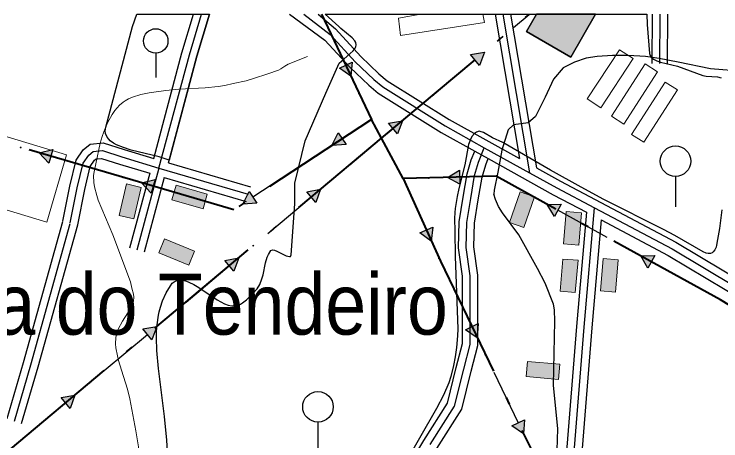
# Model space of a CAD drawing. Extents: x -64005 to -55000, y -89025 to -80000.
# Drawn here: x -59043 to -58117, y -80559 to -80000 of the extents above; entities that cross this region are included whole.
import ezdxf
from ezdxf.enums import TextEntityAlignment as Align

# ---------------------------------------------------------------- set-up
doc = ezdxf.new("R2010")
doc.units = 0
doc.header["$LTSCALE"] = 32
doc.linetypes.add('DOT_DASHED', pattern=[7.7, 5, -1.2, 0.3, -1.2])
doc.linetypes.add('LONG_DASHED', pattern=[7.5, 6, -1.5])
for name, color, linetype, lineweight in [('1', 7, 'Continuous', 25), ('16', 7, 'Continuous', 25), ('18', 7, 'Continuous', 25), ('2', 7, 'Continuous', 25), ('24', 7, 'Continuous', 25), ('3', 7, 'Continuous', 25), ('32', 7, 'Continuous', 25), ('39', 7, 'LONG_DASHED', 25), ('6', 7, 'Continuous', 25), ('7', 7, 'Continuous', 13), ('8', 7, 'Continuous', 25)]:
    doc.layers.add(name, color=color, linetype=linetype, lineweight=lineweight)
doc.layers.add('45', color=7, linetype='Continuous')

msp = doc.modelspace()

# ---------------------------------------------------------------- hatches: boundary and pattern name
at = {"layer": '18'}
for points in [[(-58444.9, -80052.94), (-58426.68, -80049.74), (-58433.02, -80067.12)], [(-58599.98, -80062.86), (-58601.46, -80081.3), (-58616.69, -80070.79)], [(-58552.21, -80142.86), (-58533.99, -80139.66), (-58540.33, -80157.04)], [(-58607.91, -80170.92), (-58626.38, -80171.99), (-58618.07, -80155.46)], [(-58997.52, -80195.16), (-59010.3, -80181.79), (-58992.33, -80177.41)], [(-58458.64, -80222.92), (-58474.89, -80214.08), (-58459.11, -80204.42)], [(-58863.17, -80234.47), (-58875.93, -80221.07), (-58857.95, -80216.72)], [(-58724.9, -80247.81), (-58743.37, -80248.88), (-58735.06, -80232.35)], [(-58659.52, -80232.77), (-58641.3, -80229.57), (-58647.64, -80246.95)], [(-58334.83, -80265.15), (-58344.4, -80249.31), (-58325.9, -80248.94)], [(-58494.36, -80279.2), (-58496.21, -80297.61), (-58511.22, -80286.81)], [(-58212.22, -80332.72), (-58221.78, -80316.88), (-58203.29, -80316.52)], [(-58766.84, -80322.68), (-58748.62, -80319.48), (-58754.96, -80336.86)], [(-58874.15, -80412.59), (-58855.93, -80409.4), (-58862.27, -80426.77)], [(-58434.72, -80405.59), (-58436.1, -80424.04), (-58451.39, -80413.63)], [(-58981.46, -80502.51), (-58963.24, -80499.31), (-58969.58, -80516.69)], [(-58373.94, -80531.71), (-58375.32, -80550.16), (-58390.61, -80539.75)]]:
    msp.add_hatch(color=256, dxfattribs=at).paths.add_polyline_path(points)
at = {"layer": '3'}
msp.add_hatch(color=256, dxfattribs=at).paths.add_polyline_path([(-58358.5, -80000), (-58371.58, -80022.88), (-58313.2, -80056.23), (-58281.07, -80000)])
at = {"layer": '7'}
for points in [[(-58895.71, -80222.52), (-58905.4, -80263.9), (-58885.93, -80268.46), (-58876.24, -80227.08)], [(-58836.11, -80243.16), (-58795.33, -80255.11), (-58789.71, -80235.92), (-58830.49, -80223.97)], [(-58379.9, -80233), (-58393.87, -80273.15), (-58374.98, -80279.72), (-58361.01, -80239.57)], [(-58319.38, -80258.65), (-58322.99, -80300.99), (-58303.06, -80302.69), (-58299.45, -80260.35)], [(-58853.24, -80312.98), (-58813.93, -80329.15), (-58806.32, -80310.66), (-58845.63, -80294.49)], [(-58323.78, -80320.93), (-58327.39, -80363.27), (-58307.46, -80364.97), (-58303.85, -80322.63)], [(-58271.06, -80320.32), (-58274.67, -80362.66), (-58254.74, -80364.36), (-58251.13, -80322.02)], [(-58372.01, -80475.07), (-58329.67, -80478.68), (-58327.97, -80458.75), (-58370.31, -80455.14)]]:
    msp.add_hatch(color=256, dxfattribs=at).paths.add_polyline_path(points)

# ---------------------------------------------------------------- linework, layer by layer
at = {"layer": '1'}
for points in [[(-58086.94, -80075.03), (-58130.16, -80071.76), (-58172.67, -80063.13), (-58197.69, -80057.93), (-58215.62, -80055.66), (-58238.24, -80054.09), (-58258.66, -80054.07), (-58278.98, -80055.61), (-58293.11, -80057.8), (-58308.62, -80062.99), (-58323.56, -80070.57), (-58336.23, -80085.09), (-58346.88, -80108.69), (-58359.83, -80134.15), (-58369.08, -80142.48), (-58388.52, -80145.26), (-58395.46, -80151.74), (-58403.78, -80178.12), (-58408.97, -80207.13), (-58414.01, -80230.79), (-58414.07, -80235.94)], [(-58331.14, -80571.64), (-58330.48, -80543.57), (-58336.26, -80486.27), (-58334.43, -80402.2), (-58334.72, -80387.32), (-58336, -80379.92), (-58347.08, -80352.71), (-58356.85, -80333.48), (-58381.47, -80289.27), (-58402.92, -80260.57), (-58408.19, -80252.09), (-58412.23, -80243.15), (-58414.07, -80235.94)]]:
    msp.add_lwpolyline(points, dxfattribs=at)
at = {"layer": '16'}
msp.add_lwpolyline([(-58281.07, -80000), (-58313.2, -80056.23), (-58371.58, -80022.88), (-58358.5, -80000)], dxfattribs=at)
at = {"layer": '18', "linetype": 'DOT_DASHED', "lineweight": 40}
msp.add_line((-58640.07, -80000), (-58574.56, -80137.93), dxfattribs=at)
at = {"layer": '18'}
for p, q in [((-58640.07, -80000), (-58608.33, -80066.83)), ((-58388.36, -80017.63), (-58367.89, -80000.48)), ((-58495.67, -80107.55), (-58438.96, -80060.03)), ((-58580.01, -80126.46), (-58574.56, -80137.93)), ((-58923.92, -80207.05), (-58994.93, -80186.28)), ((-58668.16, -80199.45), (-58729.98, -80240.08)), ((-58533.19, -80215.56), (-58502.79, -80283)), ((-58789.59, -80246.49), (-58860.56, -80225.59)), ((-58710.29, -80287.37), (-58653.58, -80239.86)), ((-58265.57, -80292.75), (-58330.37, -80257.05)), ((-58142.96, -80360.32), (-58207.75, -80324.62)), ((-58817.6, -80377.28), (-58760.9, -80329.77)), ((-58475.17, -80342.96), (-58443.05, -80409.61)), ((-58924.92, -80467.2), (-58868.21, -80419.68)), ((-58414.39, -80469.08), (-58382.28, -80535.73)), ((-59032.23, -80557.11), (-58975.52, -80509.6))]:
    msp.add_line(p, q, dxfattribs=at)
at = {"layer": '18', "linetype": 'DOT_DASHED', "lineweight": 40}
for points in [[(-62477.87, -83403.87), (-62367.98, -83378.64), (-62216.73, -83247.74), (-62089.34, -83137.49), (-61996.3, -83056.97), (-61098.84, -82280.26), (-60868.7, -82080.1), (-60312.19, -81596.09), (-60219.71, -81521.05), (-59047.52, -80569.92), (-58561.43, -80162.65), (-58367.89, -80000.48)], [(-58561.43, -80162.65), (-58574.56, -80137.93), (-58755.16, -80256.63), (-58869.5, -80222.96), (-59155.67, -80139.28), (-59177.46, -80000)], [(-56806.36, -80942.81), (-56953.76, -80909.92), (-57102.87, -80872.95), (-57268.09, -80773.37), (-57452.61, -80714.07), (-57523.68, -80743.98), (-57674.42, -80699.85), (-57727.93, -80674.98), (-57838.73, -80585.07), (-57997.82, -80458.17), (-58069.39, -80403.64), (-58117.07, -80374.59), (-58411.27, -80212.46), (-58533.19, -80215.56), (-58561.43, -80162.65)], [(-58533.19, -80215.56), (-58484.36, -80323.89), (-58375.02, -80550.79), (-58324.62, -80651.59), (-58318.83, -80776.6), (-58323.49, -80923.33), (-58331.23, -81212.92), (-58335.52, -81363.6), (-58303.61, -81482.29), (-58273.33, -81806.29), (-58260.06, -81954.23), (-58246.44, -82095.74), (-58226.31, -82245.99)]]:
    msp.add_lwpolyline(points, dxfattribs=at)
at = {"layer": '18'}
for points in [[(-58444.9, -80052.94), (-58426.68, -80049.74), (-58433.02, -80067.12)], [(-58599.98, -80062.86), (-58601.46, -80081.3), (-58616.69, -80070.79)], [(-58552.21, -80142.86), (-58533.99, -80139.66), (-58540.33, -80157.04)], [(-58607.91, -80170.92), (-58626.38, -80171.99), (-58618.07, -80155.46)], [(-58997.52, -80195.16), (-59010.3, -80181.79), (-58992.33, -80177.41)], [(-58458.64, -80222.92), (-58474.89, -80214.08), (-58459.11, -80204.42)], [(-58863.17, -80234.47), (-58875.93, -80221.07), (-58857.95, -80216.72)], [(-58724.9, -80247.81), (-58743.37, -80248.88), (-58735.06, -80232.35)], [(-58659.52, -80232.77), (-58641.3, -80229.57), (-58647.64, -80246.95)], [(-58334.83, -80265.15), (-58344.4, -80249.31), (-58325.9, -80248.94)], [(-58494.36, -80279.2), (-58496.21, -80297.61), (-58511.22, -80286.81)], [(-58212.22, -80332.72), (-58221.78, -80316.88), (-58203.29, -80316.52)], [(-58766.84, -80322.68), (-58748.62, -80319.48), (-58754.96, -80336.86)], [(-58874.15, -80412.59), (-58855.93, -80409.4), (-58862.27, -80426.77)], [(-58434.72, -80405.59), (-58436.1, -80424.04), (-58451.39, -80413.63)], [(-58981.46, -80502.51), (-58963.24, -80499.31), (-58969.58, -80516.69)], [(-58373.94, -80531.71), (-58375.32, -80550.16), (-58390.61, -80539.75)]]:
    msp.add_lwpolyline(points, close=True, dxfattribs=at)
for points in [[(-58561.43, -80162.65), (-58574.56, -80137.93), (-58612.99, -80163.19)], [(-58602.98, -80197.46), (-58561.43, -80162.65), (-58546.27, -80149.95)], [(-58524.88, -80215.35), (-58533.19, -80215.56), (-58561.43, -80162.65)], [(-58388.19, -80225.18), (-58411.27, -80212.46), (-58458.88, -80213.67)]]:
    msp.add_lwpolyline(points, dxfattribs=at)
for centre in [(-58407.52, -80033.69), (-58590.73, -80103.88), (-58514.83, -80123.6), (-59034.3, -80174.77), (-58647.27, -80185.72), (-58899.92, -80214.06), (-58622.14, -80213.52), (-58499.88, -80214.71), (-58366.29, -80237.25), (-58765.61, -80253.55), (-58729.46, -80303.43), (-58243.68, -80304.82), (-58485.93, -80320.4), (-58121.06, -80372.39), (-58836.77, -80393.34), (-58425.24, -80446.56), (-58944.08, -80483.25)]:
    msp.add_circle(centre, 0.5, dxfattribs=at)
at = {"layer": '2', "lineweight": 13}
for points in [[(-58658.56, -80055.34), (-58683.69, -80065.74), (-58687.99, -80068.17), (-58693.47, -80071.9), (-58696.42, -80073.34), (-58710.39, -80078.16), (-58729.27, -80084.47), (-58738.81, -80087.31), (-58755.66, -80090.7), (-58766.9, -80093.33), (-58775.37, -80094.84), (-58792.47, -80096.7), (-58826.97, -80098.5), (-58844.18, -80099.93), (-58866.12, -80102.96), (-58876.94, -80105.39), (-58887.66, -80108.92), (-58892.98, -80111.22), (-58897.22, -80113.51), (-58899.86, -80115.27), (-58904.69, -80119.25), (-58910.94, -80126.23), (-58914.52, -80131.41), (-58920.51, -80142.57), (-58925.48, -80154.28), (-58927.56, -80160.19), (-58930.05, -80169.26), (-58935.83, -80196.24), (-58938.19, -80206.53), (-58938.72, -80211.66), (-58938.24, -80220.46), (-58937.36, -80226.3), (-58934.47, -80237.9), (-58932.58, -80243.67), (-58928.15, -80255.15), (-58918.27, -80277.91), (-58913.67, -80289.23), (-58890.48, -80350.67)], [(-58872.98, -80624.35), (-58873.24, -80623.32), (-58873.42, -80622.24), (-58873.87, -80619.56), (-58880.13, -80566.9), (-58883.54, -80545.94), (-58891.39, -80504.22), (-58894.47, -80491.55), (-58902.39, -80466.59), (-58906.1, -80454.1), (-58907.65, -80447.81), (-58909.48, -80437.33), (-58909.91, -80431.94), (-58909.64, -80423.92), (-58907.92, -80416.27), (-58906.4, -80412.69), (-58901.1, -80402.23), (-58889.84, -80385.23), (-58887.15, -80379.37), (-58886.37, -80376.34), (-58886.14, -80370.84), (-58886.65, -80367.06), (-58888.48, -80359.34), (-58890.48, -80350.67)]]:
    msp.add_lwpolyline(points, dxfattribs=at)
at = {"layer": '24'}
msp.add_lwpolyline([(-58839.8, -80191.26), (-58853.03, -80187.17), (-58889.52, -80178.2), (-58899.62, -80175), (-58908.6, -80171.22), (-58912.5, -80169.05), (-58916.93, -80165.84), (-58918.78, -80164.08), (-58921.04, -80161.23), (-58923.12, -80156.44), (-58923.54, -80152.88), (-58922.86, -80147.97), (-58887.65, -80016.32), (-58882.26, -80000), (-58787.07, -80000), (-58803.38, -80055.23)], close=True, dxfattribs=at)
for points in [[(-58616.86, -80064.15), (-58611.03, -80058.8), (-58602.37, -80051.67), (-58598.65, -80048.11), (-58595.91, -80044.56), (-58595.05, -80042.79), (-58594.55, -80040.14), (-58595.23, -80037.18), (-58596.59, -80034.81), (-58599.71, -80031.27), (-58614.69, -80018.93), (-58617.49, -80016.28), (-58635.32, -80000), (-58213.91, -80000), (-58213.21, -80013.66)], [(-58213.21, -80013.66), (-58210.2, -80051.43), (-58209.2, -80054.25), (-58207.54, -80056.63), (-58205.02, -80058.84)], [(-58675.14, -80248.58), (-58675.04, -80221.65), (-58661.48, -80166.21), (-58634.35, -80103.52), (-58616.86, -80064.15)], [(-58205.02, -80058.84), (-58200.52, -80061.27), (-58195.99, -80062.89), (-58173.43, -80068.29), (-58140.57, -80080.33), (-58135.79, -80081.12), (-58121.11, -80082.2), (-58116.29, -80083.49)], [(-58115.41, -80256.55), (-58118.55, -80280.84), (-58120.97, -80295.4), (-58122.34, -80302.69), (-58123.1, -80305.45), (-58124.67, -80308.86), (-58126.6, -80311.49), (-58128.12, -80312.81), (-58130.25, -80313.76), (-58133.39, -80313.89), (-58136.01, -80313.33), (-58139.99, -80311.72), (-58177.04, -80290.3), (-58191.94, -80282.13), (-58270.09, -80242.96), (-58299.86, -80226.91), (-58339.86, -80204.64), (-58402.34, -80168.26), (-58415.79, -80161.93), (-58427.67, -80155.02), (-58432.07, -80153.64), (-58433.49, -80153.59), (-58436.99, -80154.65), (-58439.52, -80156.33), (-58442.91, -80160.21), (-58444.99, -80164.14), (-58447.28, -80171.01), (-58452.17, -80197.53), (-58460.02, -80228.68), (-58462.33, -80239.06), (-58464.83, -80254.74), (-58465.31, -80260), (-58465.62, -80267.93), (-58465.55, -80284.56), (-58464.82, -80317.81), (-58461.6, -80412.58), (-58461.82, -80421.73), (-58463.1, -80436.96), (-58464.82, -80449.13), (-58467.01, -80460.68), (-58470.62, -80474.88), (-58473.31, -80483.23), (-58480.01, -80499.44), (-58489.41, -80516.86), (-58532.19, -80591.5)], [(-58842.07, -80573.52), (-58842.86, -80558.45), (-58846.04, -80527.13), (-58853.83, -80464.51), (-58855.76, -80441.03), (-58856.34, -80424.03), (-58856.18, -80415.55), (-58855.62, -80407.11), (-58853.83, -80394.49), (-58852.93, -80390.3), (-58851.27, -80384.03), (-58848.41, -80375.7), (-58843.68, -80365.33), (-58838.19, -80356.05), (-58835.58, -80352.8), (-58833.31, -80350.89), (-58829.64, -80349.07), (-58827.03, -80348.5), (-58821.44, -80348.73), (-58816.98, -80349.93), (-58813.89, -80351.15), (-58807.49, -80354.4), (-58800.87, -80358.47), (-58777.03, -80374.47), (-58767.09, -80379.75), (-58762.32, -80381.5), (-58757.72, -80382.49), (-58752.62, -80382.49), (-58749.18, -80381.61), (-58746.24, -80380.13), (-58743.59, -80378.34), (-58738.43, -80374.34), (-58730.4, -80366.66), (-58724.59, -80359.84), (-58721.12, -80354.29), (-58718.18, -80346.9), (-58716.74, -80341.69), (-58713.27, -80325.84), (-58711.11, -80318.43), (-58709.7, -80315.02), (-58706.62, -80309.92), (-58704.52, -80309.02), (-58701.71, -80309.33), (-58698.42, -80310.51), (-58686.19, -80316.69), (-58682.24, -80317.8), (-58680.91, -80317.46), (-58680.32, -80316.81), (-58679.97, -80315.45), (-58675.14, -80248.58)]]:
    msp.add_lwpolyline(points, dxfattribs=at)
at = {"layer": '3'}
msp.add_lwpolyline([(-58358.5, -80000), (-58371.58, -80022.88), (-58313.2, -80056.23), (-58281.07, -80000)], close=True, dxfattribs=at)
at = {"layer": '32'}
for p, q in [((-58857.26, -80051.14), (-58857.26, -80083.14)), ((-58176.18, -80212.68), (-58176.18, -80252.68)), ((-58644.75, -80534.63), (-58644.75, -80574.63))]:
    msp.add_line(p, q, dxfattribs=at)
for centre, radius in [((-58857.26, -80035.14), 16), ((-58176.18, -80192.68), 20), ((-58644.75, -80514.63), 20)]:
    msp.add_circle(centre, radius, dxfattribs=at)
at = {"layer": '39'}
for p, q in [((-58813.28, -80053.42), (-58797.5, -80000)), ((-58196.63, -80000), (-58197.05, -80064.49)), ((-58853.07, -80201.71), (-58813.28, -80053.42)), ((-58853.07, -80201.71), (-58882.21, -80309.15)), ((-58853.07, -80201.71), (-58736, -80235.99))]:
    msp.add_line(p, q, dxfattribs=at)
at = {"layer": '39', "linetype": 'Continuous'}
for p in [(-58402.39, -80000), (-58426.77, -80175.05)]:
    msp.add_line(p, (-58367.62, -80207.92), dxfattribs=at)
for points in [[(-58663.24, -80000), (-58628.76, -80026.76), (-58595.85, -80062.66), (-58571.45, -80085.76), (-58559.82, -80095.42)], [(-58559.82, -80095.42), (-58478.02, -80146.57), (-58426.77, -80175.05)], [(-58367.62, -80207.92), (-58331.83, -80227.81), (-58282.46, -80253.82)], [(-58336.37, -80917.36), (-58295.8, -80410.35), (-58282.46, -80253.82)], [(-58282.46, -80253.82), (-58180.76, -80307.4), (-58055.69, -80382.14), (-58012.25, -80415.34), (-57993.29, -80430.34)]]:
    msp.add_lwpolyline(points, dxfattribs=at)
at = {"layer": '39'}
for points in [[(-58497.64, -80564.1), (-58465.59, -80513.64), (-58453.78, -80465.35), (-58445.34, -80432.9), (-58445.34, -80342.86), (-58450.4, -80305.66), (-58449.56, -80273.21), (-58444.49, -80241.55), (-58439.42, -80211.47), (-58434.35, -80194.06), (-58426.77, -80175.05)], [(-59042.57, -80533.44), (-59021.01, -80459.43), (-58969.28, -80273.66), (-58960.21, -80227.7), (-58952.49, -80195.45), (-58945.15, -80184.63), (-58939.36, -80180.19), (-58927.2, -80178.84), (-58901.72, -80186.95), (-58853.07, -80201.71)]]:
    msp.add_lwpolyline(points, dxfattribs=at)
at = {"layer": '6'}
for p, q in [((-58412.53, -80000), (-58380.62, -80189.25)), ((-58392.25, -80000), (-58358.48, -80201.56))]:
    msp.add_line(p, q, dxfattribs=at)
for points in [[(-58682, -80000), (-58635.61, -80034.09), (-58602.98, -80069.68), (-58578.09, -80093.25), (-58565.71, -80103.53)], [(-58644.48, -80000), (-58621.91, -80019.43), (-58588.72, -80055.63), (-58564.81, -80078.28), (-58553.93, -80087.31)], [(-58553.93, -80087.31), (-58472.94, -80137.95), (-58380.62, -80189.25)], [(-58565.71, -80103.53), (-58483.1, -80155.19), (-58439.32, -80179.51), (-58421.7, -80189.3)], [(-58421.7, -80189.3), (-58336.58, -80236.6), (-58292.98, -80259.58)], [(-58358.48, -80201.56), (-58327.07, -80219.02), (-58175.87, -80298.68), (-58050.06, -80373.85), (-58005.28, -80408.08)], [(-58292.98, -80259.58), (-58305.76, -80409.52), (-58346.34, -80916.54), (-58352.89, -80986.02), (-58360.45, -81079.14), (-58368, -81171.94), (-58373.17, -81254.38), (-58377.63, -81312.7), (-58383.47, -81392.37), (-58386, -81426.68)], [(-58273.78, -80269.68), (-58285.84, -80411.18), (-58326.4, -80918.18), (-58332.97, -80987.78), (-58340.51, -81080.76), (-58348.06, -81173.38), (-58353.23, -81255.76), (-58357.69, -81314.2), (-58363.53, -81393.83), (-58366.39, -81432.64)], [(-58273.78, -80269.68), (-58185.66, -80316.13), (-58061.31, -80390.44), (-58018.39, -80423.23), (-58002.88, -80435.51)]]:
    msp.add_lwpolyline(points, dxfattribs=at)
at = {"layer": '7'}
for points in [[(-58510.11, -80000), (-58539.26, -80005.34), (-58536.65, -80027.82), (-58426.65, -80011), (-58428.68, -80000)], [(-58231.8, -80058.33), (-58273.94, -80122.74), (-58291.79, -80111.06), (-58249.66, -80046.64)], [(-58199.95, -80075.68), (-58243.78, -80144.22), (-58259.94, -80133.88), (-58216.12, -80065.35)], [(-58173.65, -80099.36), (-58217.48, -80167.9), (-58233.64, -80157.56), (-58189.82, -80089.03)], [(-59105.63, -80144.55), (-58974.33, -80184.26), (-59000.21, -80272.65), (-59131.52, -80232.94)], [(-58895.71, -80222.52), (-58905.4, -80263.9), (-58885.93, -80268.46), (-58876.24, -80227.08)], [(-58836.11, -80243.16), (-58795.33, -80255.11), (-58789.71, -80235.92), (-58830.49, -80223.97)], [(-58379.9, -80233), (-58393.87, -80273.15), (-58374.98, -80279.72), (-58361.01, -80239.57)], [(-58319.38, -80258.65), (-58322.99, -80300.99), (-58303.06, -80302.69), (-58299.45, -80260.35)], [(-58853.24, -80312.98), (-58813.93, -80329.15), (-58806.32, -80310.66), (-58845.63, -80294.49)], [(-58323.78, -80320.93), (-58327.39, -80363.27), (-58307.46, -80364.97), (-58303.85, -80322.63)], [(-58271.06, -80320.32), (-58274.67, -80362.66), (-58254.74, -80364.36), (-58251.13, -80322.02)], [(-58372.01, -80475.07), (-58329.67, -80478.68), (-58327.97, -80458.75), (-58370.31, -80455.14)]]:
    msp.add_lwpolyline(points, close=True, dxfattribs=at)
at = {"layer": '8', "linetype": 'LONG_DASHED'}
for p, q in [((-58822.96, -80050.93), (-58807.92, -80000)), ((-58206.63, -80000), (-58207.06, -80064.65)), ((-58859.95, -80189.17), (-58822.96, -80050.93)), ((-58840.79, -80194.89), (-58733.19, -80226.39)), ((-58865.26, -80208.46), (-58891.86, -80306.53))]:
    msp.add_line(p, q, dxfattribs=at)
at = {"layer": '8'}
for p, q in [((-58803.38, -80055.23), (-58787.07, -80000)), ((-58186.63, -80000), (-58187.05, -80064.73)), ((-58840.79, -80194.89), (-58803.38, -80055.23)), ((-58846.09, -80214.18), (-58872.56, -80311.77)), ((-58846.09, -80214.18), (-58738.81, -80245.59))]:
    msp.add_line(p, q, dxfattribs=at)
at = {"layer": '8', "linetype": 'LONG_DASHED'}
for points in [[(-59051.92, -80529.78), (-59030.63, -80456.69), (-58979.02, -80271.34), (-58969.98, -80225.56), (-58961.79, -80191.34), (-58952.52, -80177.68), (-58943.24, -80170.56), (-58926.19, -80168.67), (-58898.75, -80177.4), (-58859.95, -80189.17)], [(-58528.96, -80597.51), (-58506.17, -80558.88), (-58474.91, -80509.67), (-58463.48, -80462.91), (-58455.34, -80431.62), (-58455.34, -80387), (-58455.34, -80343.54), (-58460.42, -80306.22), (-58459.54, -80272.29), (-58454.36, -80239.93), (-58449.19, -80209.23), (-58443.82, -80190.8), (-58439.32, -80179.51)]]:
    msp.add_lwpolyline(points, dxfattribs=at)
at = {"layer": '8'}
for points in [[(-59033.04, -80536.47), (-59011.4, -80462.17), (-58959.55, -80275.97), (-58950.44, -80229.83), (-58943.19, -80199.55), (-58937.79, -80191.58), (-58935.49, -80189.82), (-58928.21, -80189.01), (-58904.69, -80196.5), (-58865.26, -80208.46)], [(-58489.11, -80569.32), (-58456.27, -80517.61), (-58444.08, -80467.8), (-58435.34, -80434.18), (-58435.34, -80387), (-58435.34, -80342.17), (-58440.38, -80305.11), (-58439.58, -80274.13), (-58434.61, -80243.17), (-58429.66, -80213.71), (-58424.88, -80197.31), (-58421.7, -80189.3)]]:
    msp.add_lwpolyline(points, dxfattribs=at)

# ---------------------------------------------------------------- texts
at = {"layer": '45', "width": 0.9}
msp.add_text('Sesmaria do Tendeiro', height=80, rotation=0.007, dxfattribs=at).set_placement((-58948.15, -80420.06), align=Align.CENTER)

doc.saveas('drawing.dxf')
